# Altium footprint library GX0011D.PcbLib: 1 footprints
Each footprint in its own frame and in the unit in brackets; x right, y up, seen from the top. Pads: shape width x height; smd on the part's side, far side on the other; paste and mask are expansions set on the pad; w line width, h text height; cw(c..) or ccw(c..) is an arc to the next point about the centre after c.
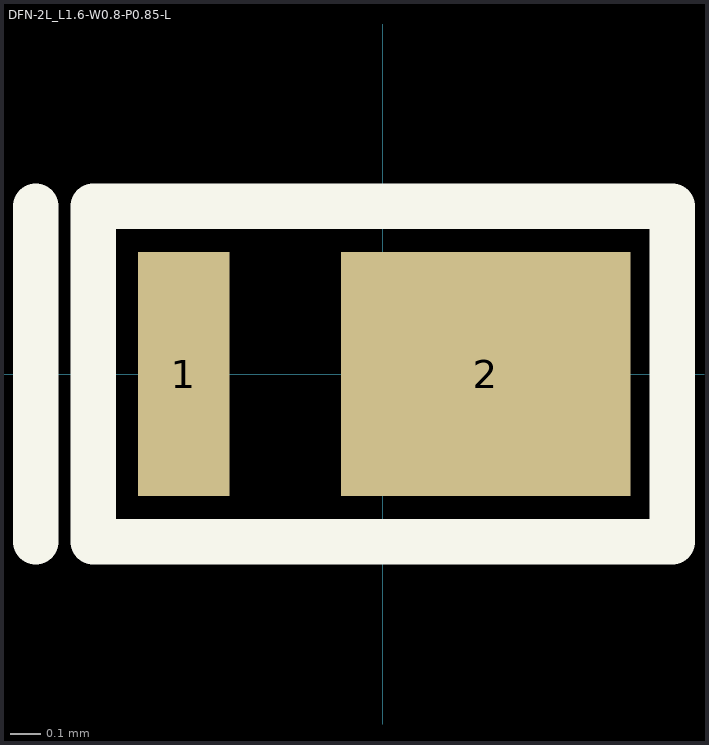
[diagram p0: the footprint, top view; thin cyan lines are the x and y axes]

## DFN-2L_L1.6-W0.8-P0.85-L [mm]
pads (2):
  rect 0.3x0.8 smd: 1(-0.653,0)
  rect 0.95x0.8 smd: 2(0.338,0)
Top Overlay:
  lines w0.15: -1.138,-0.55 -1.138,0.55 ; -0.95,-0.55 0.95,-0.55 0.95,0.55 -0.95,0.55 -0.95,-0.55
3D body "DFN-2-0.8X1.6.STEP": height 0.51, standoff 0, extent -0.805,-0.406 0.805,0.404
